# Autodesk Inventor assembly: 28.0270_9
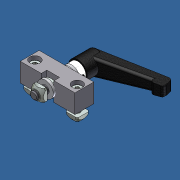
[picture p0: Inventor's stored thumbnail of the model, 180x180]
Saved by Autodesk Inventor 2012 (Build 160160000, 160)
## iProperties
Created: 2011-02
Part Number: 28.0270_9
Document SubType Name: Assembly
Designer: Administrator
Description: SLIDE CLAMPING UNIT
Vendor: S
Mass: 229.022 g
Surface Area: 188.767 cm^2
Volume: 42.7415 cm^3
Density: 5.35829 g/cm^3
Author: Administrator
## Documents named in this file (3)
- C:\Andys Backup Data\ANDY'S INVENTOR\INVENTOR LIBRARIES\PARTS LIBRARY\COMPONENTS LR\28.0270_9 SLIDE CLAMPING UNIT 2mm OFFSET..iam
- C:\Andys Backup Data\ANDY'S INVENTOR\INVENTOR LIBRARIES\PARTS LIBRARY\COMPONENTS LR\SUBCOMPONENTS\28.0270 SLIDE CLAMPING UNIT 2mm OFFSET.iam
- C:\Andys Backup Data\ANDY'S INVENTOR\INVENTOR LIBRARIES\PARTS LIBRARY\FASTENING ELEMENTS\SET SCREWS\21.9841 M4X5 FLAT POINT DIN 913.ipt
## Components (2 placed, 2 different names)
1. 28.0270 SLIDE CLAMPING UNIT 2mm OFFSET:1 [sub-assembly] — Tangent:1, Mate:1
2. 21.9841 SET SCREW M4X5 FLAT POINT DIN 913:1 — Tangent:1, Mate:1
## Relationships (2: Tangent 1, Mate 1)
- Tangent:1: 28.0270 SLIDE CLAMPING UNIT 2mm OFFSET:1 ↔ 21.9841 SET SCREW M4X5 FLAT POINT DIN 913:1
- Mate:1: 28.0270 SLIDE CLAMPING UNIT 2mm OFFSET:1 ↔ 21.9841 SET SCREW M4X5 FLAT POINT DIN 913:1
